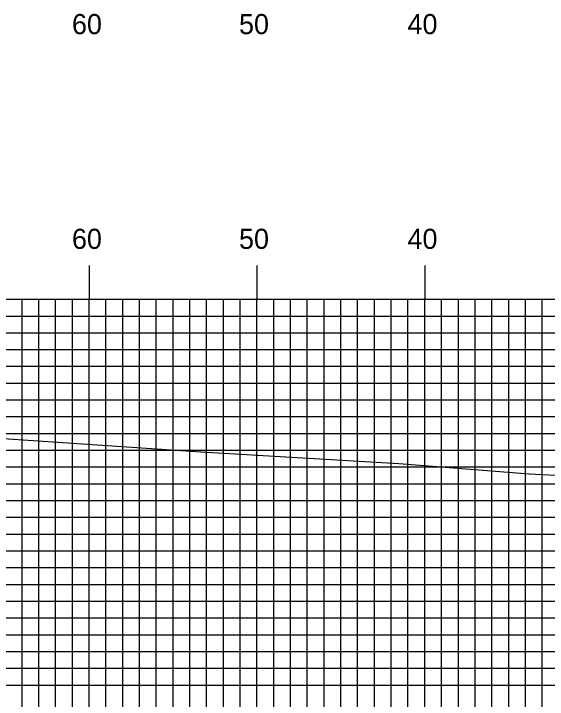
# Model space of a CAD drawing. Extents: x 1770448 to 1770792, y 442591 to 442811.
# Drawn here: x 1770549.54 to 1770581.34, y 442634.82 to 442675.68 of the extents above; entities that cross this region are included whole.
import ezdxf

# ---------------------------------------------------------------- set-up
doc = ezdxf.new("R2010")
doc.units = 0
for name, color, linetype in [('H_V ANNOTATION', 7, 'Continuous'), ('MAJOR', 7, 'Continuous'), ('MINOR', 7, 'Continuous'), ('S_Roadway_Centerline', 7, 'Continuous')]:
    doc.layers.add(name, color=color, linetype=linetype)

msp = doc.modelspace()

# ---------------------------------------------------------------- linework, layer by layer
at = {"layer": 'MAJOR'}
for p, q in [((1770554.041, 442660.669), (1770554.041, 442658.665)), ((1770564.041, 442660.669), (1770564.041, 442658.665)), ((1770574.041, 442660.669), (1770574.041, 442658.665)), ((1770474.041, 442658.665), (1770754.041, 442658.665)), ((1770474.041, 442658.665), (1770754.041, 442658.665)), ((1770554.041, 442608.665), (1770554.041, 442658.665)), ((1770564.041, 442608.665), (1770564.041, 442658.665)), ((1770574.041, 442608.665), (1770574.041, 442658.665)), ((1770474.041, 442653.665), (1770754.041, 442653.665)), ((1770474.041, 442648.665), (1770754.041, 442648.665)), ((1770474.041, 442643.665), (1770754.041, 442643.665)), ((1770474.041, 442638.665), (1770754.041, 442638.665))]:
    msp.add_line(p, q, dxfattribs=at)
at = {"layer": 'MINOR'}
for p, q in [((1770550.041, 442608.665), (1770550.041, 442658.665)), ((1770551.041, 442608.665), (1770551.041, 442658.665)), ((1770552.041, 442608.665), (1770552.041, 442658.665)), ((1770553.041, 442608.665), (1770553.041, 442658.665)), ((1770555.041, 442608.665), (1770555.041, 442658.665)), ((1770556.041, 442608.665), (1770556.041, 442658.665)), ((1770557.041, 442608.665), (1770557.041, 442658.665)), ((1770558.041, 442608.665), (1770558.041, 442658.665)), ((1770559.041, 442608.665), (1770559.041, 442658.665)), ((1770560.041, 442608.665), (1770560.041, 442658.665)), ((1770561.041, 442608.665), (1770561.041, 442658.665)), ((1770562.041, 442608.665), (1770562.041, 442658.665)), ((1770563.041, 442608.665), (1770563.041, 442658.665)), ((1770565.041, 442608.665), (1770565.041, 442658.665)), ((1770566.041, 442608.665), (1770566.041, 442658.665)), ((1770567.041, 442608.665), (1770567.041, 442658.665)), ((1770568.041, 442608.665), (1770568.041, 442658.665)), ((1770569.041, 442608.665), (1770569.041, 442658.665)), ((1770570.041, 442608.665), (1770570.041, 442658.665)), ((1770571.041, 442608.665), (1770571.041, 442658.665)), ((1770572.041, 442608.665), (1770572.041, 442658.665)), ((1770573.041, 442608.665), (1770573.041, 442658.665)), ((1770575.041, 442608.665), (1770575.041, 442658.665)), ((1770576.041, 442608.665), (1770576.041, 442658.665)), ((1770577.041, 442608.665), (1770577.041, 442658.665)), ((1770578.041, 442608.665), (1770578.041, 442658.665)), ((1770579.041, 442608.665), (1770579.041, 442658.665)), ((1770580.041, 442608.665), (1770580.041, 442658.665)), ((1770581.041, 442608.665), (1770581.041, 442658.665)), ((1770474.041, 442657.665), (1770754.041, 442657.665)), ((1770474.041, 442656.665), (1770754.041, 442656.665)), ((1770474.041, 442655.665), (1770754.041, 442655.665)), ((1770474.041, 442654.665), (1770754.041, 442654.665)), ((1770474.041, 442652.665), (1770754.041, 442652.665)), ((1770474.041, 442651.665), (1770754.041, 442651.665)), ((1770474.041, 442650.665), (1770754.041, 442650.665)), ((1770474.041, 442649.665), (1770754.041, 442649.665)), ((1770474.041, 442647.665), (1770754.041, 442647.665)), ((1770474.041, 442646.665), (1770754.041, 442646.665)), ((1770474.041, 442645.665), (1770754.041, 442645.665)), ((1770474.041, 442644.665), (1770754.041, 442644.665)), ((1770474.041, 442642.665), (1770754.041, 442642.665)), ((1770474.041, 442641.665), (1770754.041, 442641.665)), ((1770474.041, 442640.665), (1770754.041, 442640.665)), ((1770474.041, 442639.665), (1770754.041, 442639.665)), ((1770474.041, 442637.665), (1770754.041, 442637.665)), ((1770474.041, 442636.665), (1770754.041, 442636.665)), ((1770474.041, 442635.665), (1770754.041, 442635.665))]:
    msp.add_line(p, q, dxfattribs=at)
at = {"layer": 'S_Roadway_Centerline'}
msp.add_lwpolyline([(1770474.041, 442652.821), (1770480.242, 442652.875), (1770482.089, 442652.902), (1770488.882, 442652.851), (1770500.075, 442652.584), (1770501.784, 442652.524), (1770505.624, 442652.39), (1770521.011, 442651.825), (1770523.955, 442651.605), (1770528.346, 442651.404), (1770536.61, 442650.868), (1770541.267, 442650.887), (1770560.703, 442649.56), (1770560.709, 442649.559), (1770572.501, 442648.868), (1770580.263, 442648.266), (1770589.826, 442647.784), (1770599.917, 442647.161), (1770608.957, 442646.389), (1770619.82, 442645.879), (1770622.677, 442645.714), (1770639.496, 442644.896), (1770644.071, 442644.564), (1770651.96, 442644.146)], dxfattribs=at)

# ---------------------------------------------------------------- texts
at = {"layer": 'H_V ANNOTATION'}
for s, p in [('60', (1770553.013, 442674.465)), ('50', (1770562.97, 442674.465)), ('40', (1770573.013, 442674.465)), ('60', (1770553.013, 442661.665)), ('50', (1770562.97, 442661.665)), ('40', (1770573.013, 442661.665))]:
    msp.add_text(s, height=1.2, dxfattribs=at).set_placement(p)

doc.saveas('drawing.dxf')
